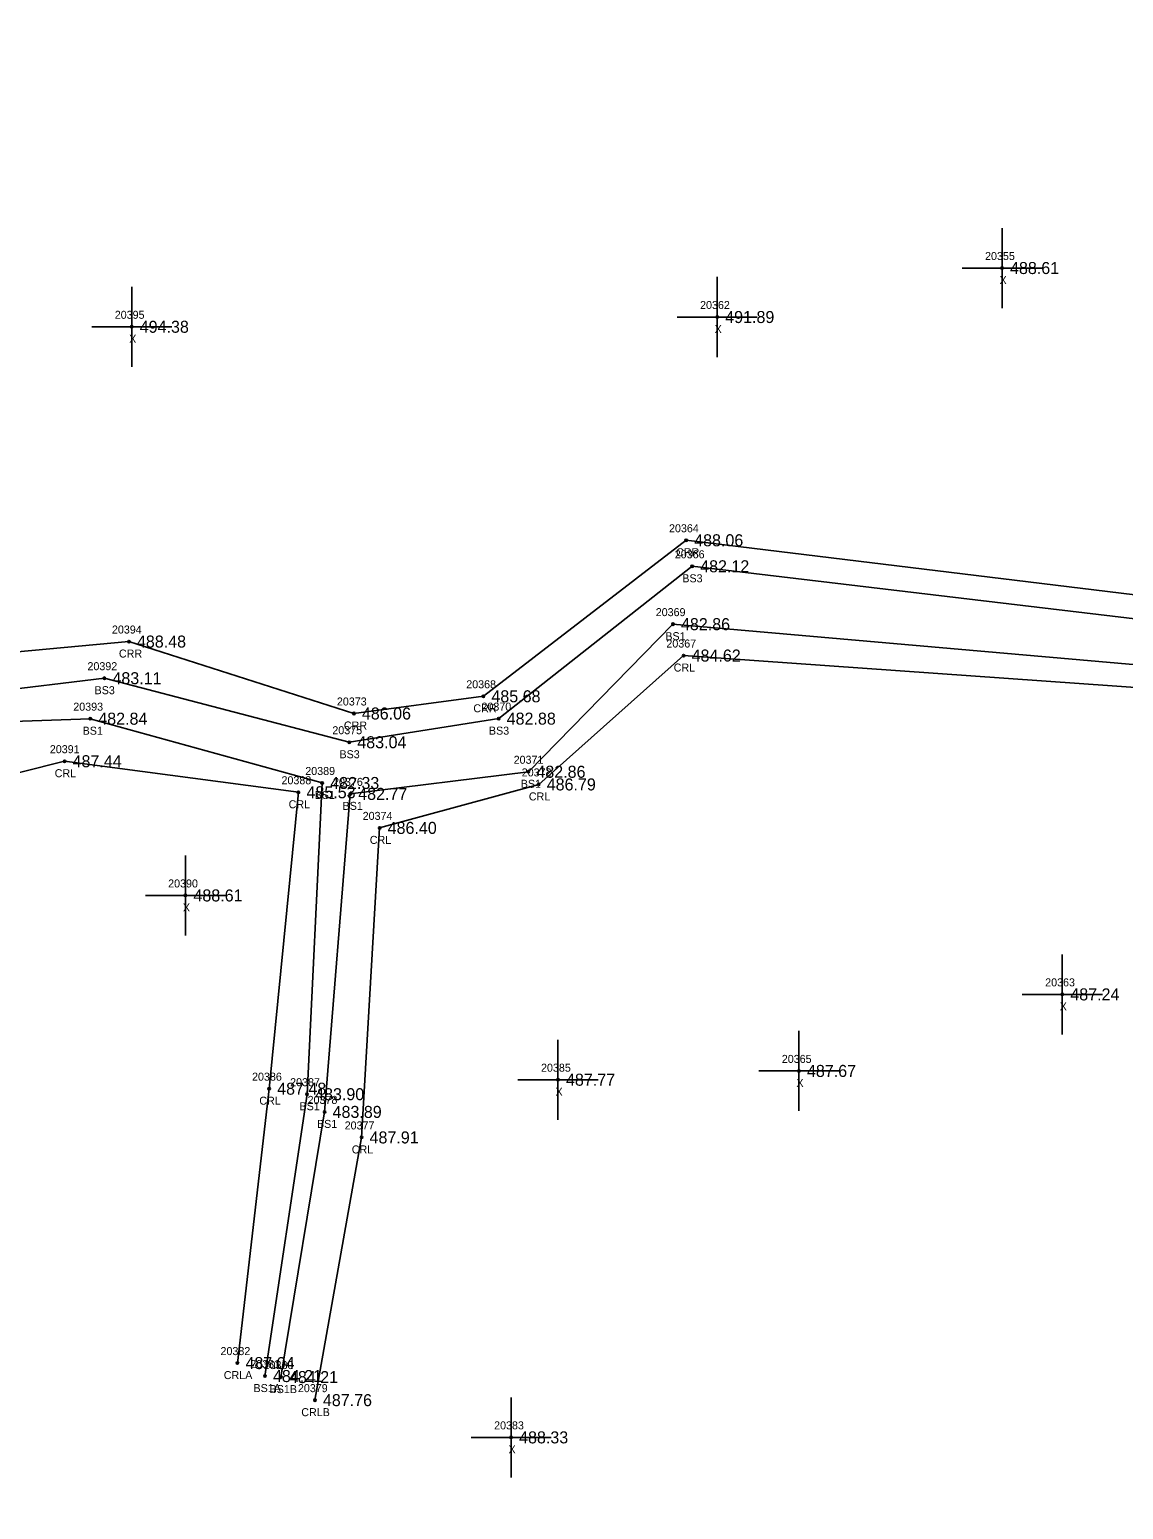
# Model space of a CAD drawing. Extents: x 1649406 to 1650436, y 896752 to 898178.
# Drawn here: x 1649551.9 to 1649688.5, y 897267.9 to 897452.8 of the extents above; entities that cross this region are included whole.
import ezdxf

# ---------------------------------------------------------------- set-up
doc = ezdxf.new("R2010")
doc.units = 0
for name, color, linetype in [('RD_DTM_BkLn2', 7, 'Continuous'), ('RD_DTM_BkLn_txCode', 7, 'Continuous'), ('RD_EX_H2O', 7, 'Continuous'), ('RD_EX_H2O_txCode', 7, 'Continuous'), ('RD_EX_Misc', 7, 'Continuous'), ('RD_EX_Misc_txCode', 7, 'Continuous'), ('RD_EX_TX_H2O_ELEV', 7, 'Continuous'), ('RD_EX_TX_Misc_ELEV', 7, 'Continuous'), ('RD_SMD_Locator', 7, 'Continuous')]:
    doc.layers.add(name, color=color, linetype=linetype)

msp = doc.modelspace()

# ---------------------------------------------------------------- linework, layer by layer
at = {"layer": 'RD_DTM_BkLn2'}
for points in [[(1649735.32, 897452.32), (1649735.42, 897430.71), (1649726.93, 897424.04), (1649733.64, 897412.51), (1649739.22, 897406.36), (1649710.88, 897394.12), (1649696.6, 897378.36), (1649634.62, 897385.73), (1649610.45, 897366.7), (1649591.79, 897363.75), (1649561.2, 897371.75), (1649517.81, 897366.5), (1649502.21, 897346.17), (1649434.27, 897348.24)], [(1649755.02, 897245.48), (1649787.66, 897308.84), (1649810.46, 897342.7), (1649823.33, 897369.5), (1649830.47, 897399.61), (1649819.89, 897394.87), (1649801.31, 897398.44), (1649793.44, 897389.39), (1649749.41, 897401.17), (1649718.21, 897392.14), (1649701.59, 897372.42), (1649632.22, 897378.5), (1649614.16, 897360.06), (1649591.9, 897357.3), (1649588.7, 897317.57), (1649583.25, 897284.44)], [(1649581.25, 897284.57), (1649586.52, 897319.78), (1649588.4, 897358.66), (1649559.43, 897366.69), (1649522.03, 897365.37), (1649504.04, 897339.98), (1649433.04, 897343.91)]]:
    msp.add_lwpolyline(points, dxfattribs=at)
at = {"layer": 'RD_EX_H2O'}
for points in [[(1649733.89, 897452.78), (1649733.23, 897431.68), (1649726.08, 897424.3), (1649730.38, 897411.38), (1649709.93, 897395.57), (1649696.43, 897381.39), (1649633.87, 897388.98), (1649608.54, 897369.49), (1649592.36, 897367.34), (1649564.26, 897376.33), (1649519.76, 897372.2), (1649499.24, 897352.4), (1649435.41, 897352.44)], [(1649753.58, 897247.01), (1649784.63, 897314.89), (1649807.13, 897344.3), (1649820.41, 897370.21), (1649823.44, 897390.83), (1649802.01, 897393.47), (1649796.5, 897387.62), (1649750.3, 897394.9), (1649722.18, 897388.11), (1649705.32, 897369.5), (1649633.55, 897374.58), (1649615.45, 897358.48), (1649595.58, 897353.05), (1649593.32, 897314.38), (1649587.49, 897281.56)], [(1649577.82, 897286.19), (1649581.78, 897320.47), (1649585.44, 897357.5), (1649556.22, 897361.38), (1649522.95, 897353.01), (1649508.94, 897339.22), (1649430.91, 897338.01)]]:
    msp.add_lwpolyline(points, dxfattribs=at)
at = {"layer": 'RD_EX_Misc'}
for p, q in [((1649673.33, 897417.99), (1649673.33, 897427.99)), ((1649668.33, 897422.99), (1649678.33, 897422.99)), ((1649564.61, 897410.65), (1649564.61, 897420.65)), ((1649637.75, 897411.87), (1649637.75, 897421.87)), ((1649632.75, 897416.87), (1649642.75, 897416.87)), ((1649559.61, 897415.65), (1649569.61, 897415.65)), ((1649571.32, 897339.61), (1649571.32, 897349.61)), ((1649566.32, 897344.61), (1649576.32, 897344.61)), ((1649680.86, 897327.25), (1649680.86, 897337.25)), ((1649675.86, 897332.25), (1649685.86, 897332.25)), ((1649617.86, 897316.59), (1649617.86, 897326.59)), ((1649647.96, 897317.69), (1649647.96, 897327.69)), ((1649642.96, 897322.69), (1649652.96, 897322.69)), ((1649612.86, 897321.59), (1649622.86, 897321.59)), ((1649612, 897271.91), (1649612, 897281.91)), ((1649607, 897276.91), (1649617, 897276.91))]:
    msp.add_line(p, q, dxfattribs=at)
at = {"layer": 'RD_SMD_Locator'}
for centre in [(1649673.33, 897422.99), (1649637.75, 897416.87), (1649564.61, 897415.65), (1649633.87, 897388.98), (1649634.62, 897385.73), (1649632.22, 897378.5), (1649564.26, 897376.33), (1649633.55, 897374.58), (1649561.2, 897371.75), (1649608.54, 897369.49), (1649559.43, 897366.69), (1649592.36, 897367.34), (1649610.45, 897366.7), (1649591.79, 897363.75), (1649556.22, 897361.38), (1649614.16, 897360.06), (1649585.44, 897357.5), (1649588.4, 897358.66), (1649615.45, 897358.48), (1649591.9, 897357.3), (1649595.58, 897353.05), (1649571.32, 897344.61), (1649680.86, 897332.25), (1649647.96, 897322.69), (1649581.78, 897320.47), (1649617.86, 897321.59), (1649586.52, 897319.78), (1649588.7, 897317.57), (1649593.32, 897314.38), (1649577.82, 897286.19), (1649581.25, 897284.57), (1649583.25, 897284.44), (1649587.49, 897281.56), (1649612, 897276.91)]:
    msp.add_circle(centre, 0.15, dxfattribs=at)

# ---------------------------------------------------------------- texts
at = {"layer": 'RD_DTM_BkLn_txCode'}
for s, p in [('20366', (1649632.45, 897386.73)), ('BS3', (1649633.39, 897383.73)), ('20369', (1649630.07, 897379.5)), ('BS1', (1649631.27, 897376.5)), ('20392', (1649559.08, 897372.75)), ('BS3', (1649559.97, 897369.75)), ('20393', (1649557.31, 897367.69)), ('20370', (1649608.3, 897367.7)), ('BS1', (1649558.48, 897364.69)), ('20375', (1649589.67, 897364.75)), ('BS3', (1649609.23, 897364.7)), ('BS3', (1649590.56, 897361.75)), ('20371', (1649612.32, 897361.06)), ('20389', (1649586.29, 897359.66)), ('BS1', (1649587.46, 897356.66)), ('20376', (1649589.76, 897358.3)), ('BS1', (1649613.21, 897358.06)), ('BS1', (1649590.95, 897355.3)), ('20387', (1649584.4, 897320.78)), ('BS1', (1649585.57, 897317.78)), ('20378', (1649586.58, 897318.57)), ('BS1', (1649587.75, 897315.57)), ('20381', (1649579.42, 897285.57)), ('20380', (1649581.09, 897285.44)), ('BS1A', (1649579.82, 897282.57)), ('BS1B', (1649581.83, 897282.44))]:
    msp.add_text(s, height=1, dxfattribs=at).set_placement(p)
at = {"layer": 'RD_EX_H2O_txCode'}
for s, p in [('20364', (1649631.73, 897389.98)), ('CRR', (1649632.62, 897386.98)), ('20394', (1649562.14, 897377.33)), ('20367', (1649631.4, 897375.58)), ('CRR', (1649563.01, 897374.33)), ('CRL', (1649632.32, 897372.58)), ('20368', (1649606.4, 897370.49)), ('20373', (1649590.24, 897368.34)), ('CRR', (1649607.29, 897367.49)), ('CRR', (1649591.11, 897365.34)), ('20391', (1649554.38, 897362.38)), ('CRL', (1649554.99, 897359.38)), ('20388', (1649583.32, 897358.5)), ('20372', (1649613.33, 897359.48)), ('CRL', (1649584.21, 897355.5)), ('CRL', (1649614.22, 897356.48)), ('20374', (1649593.46, 897354.05)), ('CRL', (1649594.35, 897351.05)), ('20386', (1649579.64, 897321.47)), ('CRL', (1649580.55, 897318.47)), ('20377', (1649591.21, 897315.38)), ('CRL', (1649592.1, 897312.38)), ('20382', (1649575.7, 897287.19)), ('CRLA', (1649576.11, 897284.19)), ('20379', (1649585.37, 897282.56)), ('CRLB', (1649585.79, 897279.56))]:
    msp.add_text(s, height=1, dxfattribs=at).set_placement(p)
at = {"layer": 'RD_EX_Misc_txCode'}
for s, p in [('20355', (1649671.21, 897423.99)), ('X', (1649673.02, 897420.99)), ('20362', (1649635.61, 897417.87)), ('20395', (1649562.49, 897416.65)), ('X', (1649637.43, 897414.87)), ('X', (1649564.29, 897413.65)), ('20390', (1649569.16, 897345.61)), ('X', (1649571, 897342.61)), ('20363', (1649678.72, 897333.25)), ('X', (1649680.54, 897330.25)), ('20365', (1649645.82, 897323.69)), ('20385', (1649615.74, 897322.59)), ('X', (1649647.65, 897320.69)), ('X', (1649617.55, 897319.59)), ('20383', (1649609.88, 897277.91)), ('X', (1649611.68, 897274.91))]:
    msp.add_text(s, height=1, dxfattribs=at).set_placement(p)
at = {"layer": 'RD_EX_TX_H2O_ELEV'}
for s, p in [('488.06', (1649634.87, 897388.23)), ('488.48', (1649565.26, 897375.58)), ('484.62', (1649634.55, 897373.83)), ('485.68', (1649609.54, 897368.74)), ('486.06', (1649593.36, 897366.59)), ('487.44', (1649557.22, 897360.63)), ('485.53', (1649586.44, 897356.75)), ('486.79', (1649616.45, 897357.73)), ('486.40', (1649596.58, 897352.3)), ('487.48', (1649582.78, 897319.72)), ('487.91', (1649594.32, 897313.63)), ('487.04', (1649578.82, 897285.44)), ('487.76', (1649588.49, 897280.81))]:
    msp.add_text(s, height=1.5, dxfattribs=at).set_placement(p)
at = {"layer": 'RD_EX_TX_Misc_ELEV'}
for s, p in [('488.61', (1649674.33, 897422.24)), ('491.89', (1649638.75, 897416.12)), ('494.38', (1649565.61, 897414.9)), ('482.12', (1649635.62, 897384.98)), ('482.86', (1649633.22, 897377.75)), ('483.11', (1649562.2, 897371)), ('482.84', (1649560.43, 897365.94)), ('482.88', (1649611.45, 897365.95)), ('483.04', (1649592.79, 897363)), ('482.33', (1649589.4, 897357.91)), ('482.86', (1649615.16, 897359.31)), ('482.77', (1649592.9, 897356.55)), ('488.61', (1649572.32, 897343.86)), ('487.24', (1649681.86, 897331.5)), ('487.67', (1649648.96, 897321.94)), ('487.77', (1649618.86, 897320.84)), ('483.90', (1649587.52, 897319.03)), ('483.89', (1649589.7, 897316.82)), ('484.21', (1649582.25, 897283.82)), ('484.21', (1649584.25, 897283.69)), ('488.33', (1649613, 897276.16))]:
    msp.add_text(s, height=1.5, dxfattribs=at).set_placement(p)

doc.saveas('drawing.dxf')
